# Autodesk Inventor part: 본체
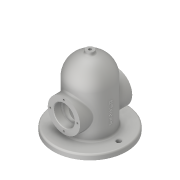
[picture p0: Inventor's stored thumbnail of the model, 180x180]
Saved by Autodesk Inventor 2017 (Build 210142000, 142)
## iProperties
Created: 2019-11
Part Number: 본체
Material: Aluminum 6061
Document SubType Name: Modeling
Designer: 1-11-lg
Density: 2.7 g/cm^3
Appearance: Aluminum - Flat
Mass: 1106.12 g
Surface Area: 883.263 cm^2
Volume: 409.676 cm^3
Author: 1-11-lg
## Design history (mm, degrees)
sketch "Sketch1"
  geometry: C1 r 70 at (0, 0); 1 further point
  constraints: 1 centre point, 1 coincident
  dimensions: "d0" = 140 diameter of C1
extrude "Extrusion1" new body sketch "Sketch1" distance "d1" = 10; taper "d2" = 0 deg
sketch "Sketch2"
  geometry: C1 r 70 at (0, 0) reference; C2 r 40 at (0, 0)
  constraints: 1 centre point, 1 coincident
  dimensions: "d3" = 80 diameter of C2
extrude "Extrusion2" join sketch "Sketch2" distance "d4" = 80; taper "d5" = 0 deg
sketch "Sketch3"
  geometry: L1 (90, 40)-(90, 0); L2 (90, 0)-(130, 0); L3 (90, -40)-(90, 40) reference; A1 r 40 centre (90, 0) between (130, 0) and (90, 40); 1 further point
  constraints: 4 end point, 2 point on circle, 1 centre point, 1 collinear, 1 horizontal, 1 horizontal alignment, 1 vertical
  dimensions: "d7" = 80 diameter of A1
revolve "Revolution1" sketch "Sketch3" stored, may be unused: angle "d8" = 90 deg
sketch "Sketch4"
  geometry: C1 r 70 at (0, 0) reference; C2 r 30 at (0, 0)
  constraints: 1 centre point, 1 coincident
  dimensions: "d9" = 60 diameter of C2
extrude "Extrusion3" cut sketch "Sketch4" distance "d10" = 90; taper "d11" = 0 deg
sketch "Sketch5"
  geometry: L1 (90, 0)-(120, 0); L2 (90, 30)-(90, 0); L3 (90, -30)-(90, 30) reference; A1 r 30 centre (90, 0) between (120, 0) and (90, 30); 1 further point
  constraints: 4 end point, 2 point on circle, 1 centre point, 1 collinear, 1 horizontal, 1 horizontal alignment, 1 vertical
  dimensions: "d12" = 60 diameter of A1
revolve "Revolution2" sketch "Sketch5" stored, may be unused: angle "d13" = 90 deg
workplane "Work Plane1"
sketch "Sketch6"
  geometry: L1 (-70, 0)-(70, 0) reference; C1 r 31 at (0, 50); 1 further point
  constraints: 1 centre point, 1 vertical alignment
  dimensions: "d15" = 62 diameter of C1; "d16" = 50 distance from line of L1 C1.centre
extrude "Extrusion4" join sketch "Sketch6" stored distance "d17" = 100; taper "d18" = 0 deg
mirror "Mirror1"
sketch "Sketch7"
  geometry: C1 r 31 at (0, 0) reference; C2 r 20 at (0, 0); 1 further point
  constraints: 1 centre point, 1 coincident
  dimensions: "d19" = 40 diameter of C2
extrude "Extrusion5" cut sketch "Sketch7" distance "d20" = 15; taper "d21" = 0 deg
sketch "Sketch8"
  geometry: L1 (0, 0)-(0, 26); C1 r 31 at (0, 0) reference; 2 further points
  constraints: 2 end point, 1 coincident, 1 vertical
  dimensions: "d22" = 26 distance of L1.start L1.end
hole "Hole1" sketch "Sketch8" at (0, 26) diameter "d23" = 3.242; stored, may be unused: countersink angle "d27" = 90 deg, drill point angle "d29" = 118 deg; dims "d24" = 8, "d25" = 4, "d26" = 2, "d28" = 10
pattern_circular "Circular Pattern1" dims angle "d31" = 360 deg
sketch "Sketch9"
  geometry: C1 r 20 at (0, 0) reference; C2 r 16.5 at (0, 0); 1 further point
  constraints: 1 centre point, 1 coincident
  dimensions: "d33" = 33 diameter of C2
extrude "Extrusion6" cut sketch "Sketch9" stored distance "d34" = 100; taper "d35" = 0 deg
sketch "Sketch10"
  geometry: C1 r 16.5 at (0, 0) reference; C2 r 31 at (0, 0) reference; C3 r 20 at (0, 0); 1 further point
  constraints: 1 centre point, 1 coincident
  dimensions: "d36" = 40 diameter of C3
extrude "Extrusion7" cut sketch "Sketch10" distance "d37" = 15; taper "d38" = 0 deg
sketch "Sketch11"
  geometry: L1 (0, 0)-(0, 26); C1 r 31 at (0, 0) reference; 2 further points
  constraints: 2 end point, 1 coincident, 1 vertical
  dimensions: "d39" = 26 distance of L1.start L1.end
hole "Hole2" sketch "Sketch11" at (0, 26) diameter "d40" = 3.242; stored, may be unused: countersink angle "d44" = 90 deg, drill point angle "d46" = 118 deg; dims "d41" = 8, "d42" = 4, "d43" = 2, "d45" = 10
pattern_circular "Circular Pattern2" dims angle "d48" = 360 deg
workplane "Work Plane2"
sketch "Sketch12"
  geometry: C1 r 7.5 at (0, 0); 1 further point
  constraints: 1 centre point, 1 coincident
  dimensions: "d51" = 15 diameter of C1
extrude "Extrusion8" join sketch "Sketch12" stored distance "d52" = 15; taper "d53" = 0 deg
sketch "Sketch13"
  geometry: C1 r 7.5 at (0, 0) reference; 1 further point
  constraints: 1 coincident
hole "Hole3" sketch "Sketch13" at (0, 0) diameter "d54" = 5.188; stored, may be unused: countersink angle "d58" = 90 deg, drill point angle "d60" = 118 deg; dims "d55" = 20, "d56" = 4, "d57" = 2, "d59" = 20
sketch "Sketch14"
  geometry: L1 (0, 0)-(-55, 0); L2 (0, 0)-(55, 0); C1 r 70 at (0, 0) reference; C2 r 4.5 at (-55, 0); C3 r 4.5 at (55, 0)
  constraints: 4 end point, 2 centre point, 2 coincident, 2 horizontal, 1 equal radius
  dimensions: "d61" = 55 distance of L1.start L1.end; "d62" = 55 distance of L1.start L2.end; "d63" = 9 diameter of C3
extrude "Extrusion9" cut sketch "Sketch14" stored distance "d64" = 15; taper "d65" = 0 deg
workplane "Work Plane3"
sketch "Sketch15"
  geometry: L1 (70.739, -3.002)-(29.261, -3.002); L2 (29.261, -3.002)-(29.261, 3.002); L3 (29.261, 3.002)-(70.739, 3.002); L4 (70.739, 3.002)-(70.739, -3.002); L5 (0, 70)-(0, -70) reference; L6 (50, -3.002)-(50, 3.002); L7 (70.739, 0)-(29.261, 0); 3 further points
  constraints: 6 midpoint, 4 end point, 1 horizontal alignment, 2 other
  dimensions: "d68" = 50 distance between parallel lines of L6 L5
emboss "Emboss1" sketch "Sketch15" dims "d2" = 0, "d69" = 0.5, "d70" = 0
chamfer "Chamfer1" distance "d71" = 1; stored, may be unused: second distance "d72" = 2, angle "d73" = 45 deg
fillet "Fillet1" dims "d74" = 0.3
fillet "Fillet2" dims "d75" = 3
fillet "Fillet3" dims "d76" = 3
fillet "Fillet4" dims "d77" = 3
body "Solid1"
other parameters: "d50" = -135, "d66" = 80.5
